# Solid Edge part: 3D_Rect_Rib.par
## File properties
Author: hullrw
Template: ansi part.par
Last saved by: hullrw
Revision: 1
Application: Solid Edge
Accuracy: 0.990
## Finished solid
Body 1: solid body, 150 faces, 444 edges, 296 vertices.
  Faces by surface: plane 90, cylinder 31, swept 29
  Edges by curve: line 324, circle 62, spline 58
Bounding box of the edges (mm; curved faces can reach further): 512.419 x 83.915 x 3.175, from (0.8411, 4.4908, 0) to (513.2599, 88.4054, 3.175).
Cylindrical faces by radius (mm): R0.2713 x1, R0.3706 x1, R0.3908 x1, R0.5643 x1, R0.6103 x1, R0.6358 x1, R0.7104 x1, R0.7303 x1, R0.7424 x1, R0.8087 x1, R0.8588 x1, R0.8755 x1, R0.8914 x1, R0.9243 x1, R0.9513 x1, R0.998 x1, R1.0215 x1, R1.1727 x1, R1.3484 x1, R1.5329 x1, R1.5658 x1, R1.6041 x1, R1.6362 x1, R1.6471 x1, R1.6841 x1, R1.7237 x1, R1.7877 x1, R4.4692 x1, R4.6551 x1, R10.6728 x1, R16.3696 x1
Planar faces by outward normal: +x 3, +y 4, +z 1, -x 6, -y 3, -z 1, oblique 72
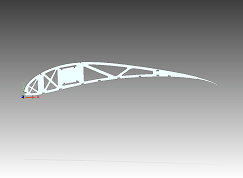
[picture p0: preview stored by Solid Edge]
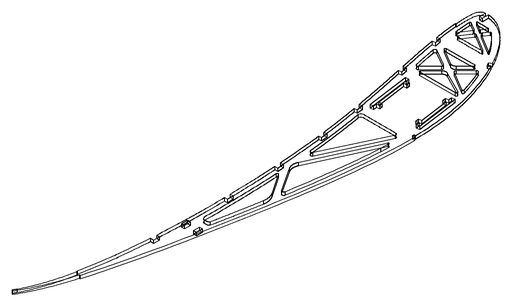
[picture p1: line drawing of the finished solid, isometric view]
